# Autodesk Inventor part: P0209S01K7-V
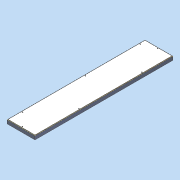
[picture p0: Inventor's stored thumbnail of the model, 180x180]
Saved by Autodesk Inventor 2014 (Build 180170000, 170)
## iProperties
Created: 2011-04
Part Number: P0209S01K7-V
Document SubType Name: Modeling
Designer: david.appleford
Density: 0.20816 g/cm^3
Description: 0.5w x 2.25w 01 Panel - 7 Locks
Mass: 24000 g
Surface Area: 34183.4 cm^2
Volume: 115296 cm^3
Cost Center: £95.00
Material: Generic
Appearance: Wood (Pine)
Justset: False
Title: 0.5w x 2.25w 01 Panel - 7 Locks
Author: david.appleford
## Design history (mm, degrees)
sketch "Sketch1"
  geometry: L1 (0, 0)-(610, 0); L2 (610, 0)-(610, 2745); L3 (610, 2745)-(0, 2745); L4 (0, 2745)-(0, 0); L5 (34, 2711)-(576, 2711); L6 (576, 2711)-(576, 34); L7 (576, 34)-(34, 34); L8 (34, 34)-(34, 2711)
  constraints: 16 end point, 4 parallel, 2 perpendicular, 1 horizontal, 3 other
  dimensions: "d0" = 610 distance between parallel lines of L2 L4 (= 0.5 x w); "d1" = 2745 distance between parallel lines of L1 L3 (= 2.25 x w); "d2" = 34 distance between parallel lines of L5 L3 (= 0.5 x t); "d29" = 2677 distance between parallel lines of L7 L5 (derived); "d30" = 542 distance between parallel lines of L6 L8 (derived)
extrude "Extrusion1" new body sketch "Sketch1" distance "d3" = 68 (= t); taper "d4" = 0 deg
sketch "Sketch2"
  geometry: L1 (576, 2711)-(576, 34) reference; L2 (34, 2711)-(576, 2711) reference; L3 (34, 34)-(34, 2711) reference; L4 (576, 34)-(34, 34) reference; L5 (566, 2701)-(566, 44); L6 (566, 44)-(44, 44); L7 (44, 44)-(44, 2701); L8 (44, 2701)-(566, 2701); 1 further point
  constraints: 8 end point, 3 other
  dimensions: "d5" = 10 distance between parallel lines of L8 L2
extrude "Extrusion2" join sketch "Sketch2" distance "d6" = 6 (= sw); taper "d7" = 0 deg
sketch "Sketch3"
  geometry: L1 (-44, 2701)-(-566, 2701) reference; L2 (-566, 2701)-(-566, 44) reference; L3 (-44, 44)-(-44, 2701) reference; L4 (-566, 44)-(-44, 44) reference; 1 further point
extrude "Extrusion3" join sketch "Sketch3" distance "d8" = 6 (= sw); taper "d9" = 0 deg
sketch "Sketch4"
  geometry: L1 (34, 2711)-(576, 2711) reference; L2 (576, 2711)-(576, 34) reference; L3 (576, 34)-(34, 34) reference; L4 (34, 34)-(34, 2711) reference; 8 further points
  constraints: 4 vertical alignment
  dimensions: "d10" = 28 distance from line of point (305, 2683) L1 (= k); "d13" = 28 distance from line of point (62, 305) L4 (= k); "d14" = 305 horizontal distance of point (305, 2683) point (0, 0) (= 0.25 x w); "d16" = 305 vertical distance of point (62, 305) point (0, 0) (= 0.25 x w); "d17" = 1220 distance of point (62, 305) point (62, 1525) (= w); "d19" = 610 vertical distance of point (548, 915) point (62, 305) (= 0.5 x w); "d20" = 1220 distance of point (548, 915) point (548, 2135) (= w); "d31" = 1067.5 distance of point (62, 1525) point (62, 2592.5); "d32" = 28 distance from line of point (305, 62) L3 (= d13)
hole "Hole1" sketch "Sketch4" at (305, 2683), (62, 1525), (62, 305), (548, 2135), (548, 915), (62, 2592.5), (305, 62) diameter "d22" = 16.3; stored, may be unused: countersink angle "d26" = 90 deg, drill point angle "d28" = 118 deg; dims "d23" = 6, "d24" = 4, "d25" = 2, "d27" = 6
body "Solid1"
node "Projected Loop1"
other parameters: "w" = 1220 [user parameter; used in 7 equation terms], "t" = 68 [user parameter; used in 2 equation terms], "e" = 16 [user parameter], "sw" = 6 [user parameter; used in 2 equation terms], "sc" = 9 [user parameter], "sf" = 12 [user parameter], "k" = 28 [user parameter; used in 2 equation terms], "hd" = 12 [user parameter]
